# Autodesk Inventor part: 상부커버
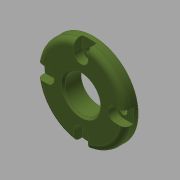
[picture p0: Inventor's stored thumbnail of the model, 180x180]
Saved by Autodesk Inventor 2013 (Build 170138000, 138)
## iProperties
Created: 2019-01
Part Number: 상부커버
Material: 알루미늄 6061
Document SubType Name: Modeling
Designer: mduedu
Density: 1 g/cm^3
Author: mduedu
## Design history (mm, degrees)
sketch "스케치1"
  geometry: L1 (0, 0)-(7, 0); L2 (7, 0)-(7, 25); L3 (7, 25)-(0, 25); L4 (0, 25)-(0, 0); L5 (7, 0)-(10, 0); L6 (10, 0)-(10, 14); L7 (10, 14)-(7, 14); L8 (7, 14)-(7, 0)
  constraints: 16 end point, 4 parallel, 2 horizontal, 2 perpendicular
  dimensions: "d0" = 50 diameter of L3 L1; "d2" = 10 distance between parallel lines of L6 L4; "d3" = 7 distance of L2.end L3.end; "d4" = 28 diameter of L7 L5
revolve "회전1" sketch "스케치1" stored, may be unused: angle "d5" = 90 deg
sketch "스케치2"
  geometry: C1 r 10 at (0, 0); 1 further point
  constraints: 1 centre point, 1 coincident
  dimensions: "d6" = 20 diameter of C1
extrude "돌출1" cut sketch "스케치2" stored distance "d7" = 10; taper "d8" = 0 deg
chamfer "모따기1" distance "d9" = 1; stored, may be unused: second distance "d10" = 2, angle "d11" = 45 deg
fillet "모깎기1" dims "d12" = 3
sketch "스케치3" dims "d13" = 38
  geometry: 6 further points
  constraints: 2 vertical alignment, 1 coincident, 7 other
  dimensions: "d16" = 360 deg dimension on point (0, 0) point (0, 19) (derived)
chamfer "모따기2" distance "d18" = 1; stored, may be unused: second distance "d19" = 2, angle "d20" = 45 deg
sketch "스케치4"
  geometry: 4 further points
  constraints: 4 other
hole "구멍1" sketch "스케치4" at (-19, 0), (0, -19), (19, 0), (0, 19) diameter "d21" = 4.5; stored, may be unused: countersink angle "d25" = 90 deg, drill point angle "d27" = 0 deg; dims "d22" = 6, "d23" = 8, "d24" = 4.6, "d26" = 8
sketch "스케치5"
  geometry: L1 (-4, 0)-(-4, 5.678); L2 (4, 0)-(4, 5.678); A1 r 4 centre (0, 0) between (-2.841, 2.816) and (2.841, 2.816) reference; A2 r 25 centre (0, -19) between (-4, 5.678) and (4, 5.678) reference; A3 r 4 centre (0, 0) between (-4, 0) and (4, 0); A4 r 25 centre (0, -19) between (4, 5.678) and (-4, 5.678); A5 r 4 centre (0, 0) between (4, 0) and (-4, 0); 1 further point
  constraints: 10 point on circle, 4 end point, 3 centre point, 2 coincident, 2 tangent, 1 parallel, 1 vertical
extrude "돌출2" cut sketch "스케치5" stored distance "d28" = 10; taper "d29" = 0 deg
node "솔리드1"
pattern_circular "원형 패턴1" dims angle "d31" = 360 deg
